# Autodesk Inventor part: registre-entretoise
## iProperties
Author: chr
Created: 2001-06
Part Number: registre-entretoise
Material: Par défaut
Document SubType Name: Modélisation
Designer: chr
Control State: 0
Master: False
Checked Out: False
PropertySet Name: Design Tracking Control
Shininess: 20.0
PropertySet Name: _Private Model Information
Length Units: 11269
Angle Units: 11286
Time Units: 11279
Mass Units: 11290
Length Display Precision: 3
Angle Display Precision: 2
Compacted: False
Density: 0.0
Volumn: 0.0
Area: 0.0
PropertySet Name: Model Information
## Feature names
1. Extrusion1
2. Extrusion2
